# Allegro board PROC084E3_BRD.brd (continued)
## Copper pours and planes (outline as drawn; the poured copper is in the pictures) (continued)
V12V0_VSUP1 on BOTTOM (solid shape): 31.73,135.3 33.87,135.3 33.87,133.63 33.91,133.59 33.91,133.49 34.26,133.14 34.26,131.69 35.3,131.69 35.3,131.36 34.26,131.36 34.26,131.27 33.66,131.27 33.58,131.19 33.29,131.19 33.29,132.16 29.87,132.16 29.87,133.1 26.34,133.1 26.34,134.38 26.33,134.38 17.14,134.38 17.14,137.07 31.73,137.07
V12V0_VSUP2 on BOTTOM (solid shape): 31.78,144.13 33.91,144.13 33.91,142.47 33.95,142.43 33.95,142.32 34.3,141.97 34.3,140.53 35.34,140.53 35.34,140.2 34.3,140.2 34.3,140.1 33.7,140.1 33.62,140.02 33.33,140.02 33.33,141 29.91,141 29.91,141.93 26.38,141.93 26.38,143.22 26.37,143.22 17.19,143.22 17.18,143.23 17.18,146.01 31.78,146.01
V12V0_VSUP3 on BOTTOM (solid shape): 31.85,153.03 33.99,153.03 33.99,151.37 34.02,151.33 34.02,151.22 34.37,150.87 34.37,149.43 35.42,149.43 35.42,149.09 34.37,149.09 34.37,149 33.78,149 33.7,148.92 33.41,148.92 33.41,149.9 29.99,149.9 29.99,150.83 26.46,150.83 26.46,152.11 26.45,152.12 17.26,152.12 17.26,154.7 31.85,154.7
VBAT_LIN1 on BOTTOM (solid shape): 14.11,141.79 14.09,141.79 14.09,139.15 14.11,139.15 14.11,137.86 16.08,137.86 16.08,135.61 13.87,135.61 13.63,135.84 13.63,136.94 12.68,136.94 12.68,137.45 12.68,137.46 11.44,138.92 10.81,137.11 10.83,137 10.74,136.94 10.37,136.94 10.37,142.06 14.11,142.06
VBAT_LIN2 on BOTTOM (solid shape): 16.4,144.44 9.7,144.44 9.7,143.78 9.21,143.78 8.32,142.9 3.76,142.9 3.76,146.15 16.4,146.15
VBAT_LIN3 on BOTTOM (solid shape): 14.9,155.59 15.51,155.59 15.51,155.53 16.2,155.53 16.2,153.34 12.89,153.34 12.89,154.67 10.49,154.67 10.49,157.3 14.9,157.3
VCC_3V3 on TOP: 75.08,140.2 79.53,140.2 79.78,140.45 79.78,143.7 79.53,143.96 75.08,143.96 74.83,143.7 74.83,140.45
VCC_3V3 on TOP: 94.11,44.19 93.85,44.44 90.6,44.44 90.35,44.19 90.35,34.43 90.73,34.05 93.52,34.05 94.11,34.64
VCC_3V3 on BOTTOM: 39.07,114.85 39.07,111.09 39.12,111.04 40.11,111.04 40.23,111.17 40.23,114.9 40.13,115 39.22,115
VCC_3V3 on BOTTOM: 43.74,98.08 46.53,98.08 46.79,98.34 46.79,99.74 46.53,99.99 43.74,99.99 43.48,99.74 43.48,98.34
VCC_3V3 on BOTTOM: 59.74,99.74 60.55,99.74 60.68,99.86 60.68,101.39 60.88,101.59 61.54,101.59 61.85,101.89 61.85,103.65 61.7,103.8 59.82,103.8 59.69,103.67 59.69,100.7 59.61,100.62 59.61,99.86
VCC_3V3 on BOTTOM: 51,103.55 51,99.79 51.05,99.74 52.04,99.74 52.17,99.86 52.17,103.6 52.07,103.7 51.16,103.7
VCC_3V3 on L05_PWR1: 87,24.27 87,16.65 84.96,14.62 81.61,14.62 81.65,14.58 81.65,8.02 1.02,8.02 1.02,196.48 23.75,196.48 23.75,152.65 42.82,152.65 43.1,152.37 43.1,137.38 58.9,137.38 59.49,136.79 59.49,118.81 57.91,117.24 41.15,117.24 40.39,116.47 40.39,110.89 46.77,104.5 50.97,104.5 52.41,103.06 52.41,101.03 53.18,100.25 55.63,100.25 55.63,104.41 74.93,123.71 74.93,143.65 75.44,144.16 85.34,144.16 85.34,140.6 91.82,134.13 91.82,118.25 92.38,117.69 93.98,117.69 95.53,116.14 95.53,111.8 91.82,108.09 91.82,88.58 90.09,86.86 90.09,66.69 89.92,66.51 89.92,44.08 93.09,40.91 93.09,30.37 ; 40 cut-outs
VCC_5V0 on TOP: 75.34,144.46 79.43,144.46 79.68,144.72 79.68,147.82 79.43,148.07 75.34,148.07 75.08,147.82 75.08,144.72
VCC_5V0 on TOP: 90.45,68.32 92.79,68.32 92.99,68.52 99.49,68.52 99.64,68.37 99.64,65.95 99.06,65.37 93.65,65.37 92.1,66.92 90.45,66.92 90.35,67.02 90.35,68.21
VCC_5V0 on L05_PWR1: 25.15,196.48 101.19,196.48 101.19,8.02 81.99,8.02 81.99,14.14 82.14,14.29 85.01,14.29 87.38,16.65 87.38,65.75 90.45,68.82 90.45,86.45 92.2,88.2 92.2,107.99 95.28,111.06 95.28,116.96 94.23,118 74.55,118 61.82,105.27 61.77,105.27 57.09,100.59 52.99,100.59 52.99,103.03 51,105.02 48.13,105.02 40.77,112.38 40.77,130.82 25.15,146.45
VCC_12V0 on TOP: 93.9,88.86 93.9,93.54 93.65,93.79 90.12,93.79 89.87,93.54 89.87,88.74 89.1,87.98 70.69,87.98 66.75,91.91 66.75,124.01 65.05,125.71 61.25,125.71 61.23,125.69 51.4,125.69 48.67,128.42 33.37,128.42 33.35,128.44 35.11,128.44 35.11,155.56 26.78,155.56 26.78,129.21 30.55,125.44 47.08,125.44 49.61,122.9 64.29,122.9 65.61,121.58 65.61,90.06 71.48,84.19 93.98,84.19 94.84,85.05 94.84,87.92
VCC_PROFIB on TOP (solid shape): outline of 110 points within 6.93,112.51 16.94,122.29
VCC_RS485 on TOP: 29.82,119.78 29.82,104 30.35,103.47 35.94,103.47 36.35,103.88 36.35,119.78 36.07,120.06 30.1,120.06
VCC_RS485 on BOTTOM: 30.53,117.64 34.52,117.64 34.72,117.85 34.72,120.92 34.32,121.33 30.58,121.33 30.48,121.22 30.48,117.69
VDD_1V0 on BOTTOM: 59.61,97.63 59.61,93.82 58.95,93.16 58.95,91.68 59.69,90.95 61.24,90.95 61.49,91.2 61.49,95.39 61.37,95.52 60.83,95.52 60.6,95.75 60.6,97.65 59.64,97.65
VDD_1V0 on L05_PWR1: 53.85,91.71 53.85,96.66 54.36,97.17 62.23,97.17 63.68,95.72 63.68,80.05 62.23,78.6 62.23,70.25 55.5,63.51 50.04,63.51 48.77,64.78 47.57,64.78 47.35,64.56 47.35,57.85 45.34,55.84 45.34,52.01 46,51.35 55.24,51.35 57.45,53.56 60.22,53.56 60.58,53.2 60.58,52.62 59.64,51.68 59.64,39.89 58.75,39 53.72,39 51.83,40.9 51.04,40.9 50.85,41.09 50.85,43.22 49.71,44.36 49.71,44.87 50.88,46.04 50.88,47.44 49.91,48.4 39.12,48.4 35.56,51.96 35.56,57.04 34.01,58.59 34.01,58.87 35.18,60.04 35.18,62.12 42.98,69.92 51.99,69.92 53.7,71.62 53.7,74.28 52.68,75.3 52.68,75.88 54.1,77.31 54.1,78.37 52.83,79.64 40.26,79.64 35.56,84.34 35.56,87.77 34.09,89.25 34.09,89.58 35.18,90.67 35.18,93.06 36.5,94.38 41.27,94.38 45.72,89.93 52.07,89.93
VDD_1V8 on BOTTOM: 39.17,108.93 39.17,105.12 38.51,104.46 38.51,101.03 39.24,100.29 47.09,100.29 48.36,99.02 48.36,90.06 49.4,89.02 59.89,89.02 59.92,89.04 61.87,89.04 67.06,83.86 67.06,70.68 67.41,70.32 68.2,70.32 68.28,70.24 71.85,70.24 72.15,70.55 72.15,73.1 71.52,73.74 71.23,73.74 71.21,73.72 68.68,73.72 68.68,85.13 63.6,90.21 51.03,90.21 49.35,91.89 49.35,99.91 47.55,101.72 42.42,101.72 41.73,102.4 41.73,104.69 41.05,105.37 41.05,106.69 40.92,106.82 40.39,106.82 40.16,107.05 40.16,108.96 39.19,108.96
VDD_2V5 on BOTTOM: 51.1,97.63 51.1,93.82 50.44,93.16 50.44,91.68 51.18,90.95 52.73,90.95 52.98,91.2 52.98,95.39 52.86,95.52 52.32,95.52 52.1,95.75 52.1,97.65 51.13,97.65
VDD_2V5 on L05_PWR1: 50.61,100.31 53.47,97.45 53.47,91.84 51.94,90.31 45.85,90.31 41.02,95.14 37.47,95.14 35.18,92.85 35.18,84.22 40.13,79.26 52.7,79.26 53.42,78.55 53.42,77.21 52.3,76.09 52.3,75.12 53.26,74.16 53.26,71.69 51.99,70.42 42.98,70.42 35.18,62.63 35.18,51.7 38.86,48.02 49.78,48.02 50.16,47.64 50.16,40.53 48.77,39.13 32.13,39.13 29.46,41.8 29.46,90.87 30.9,92.31 30.9,96.93 35.03,101.06 40.06,101.06 43.43,97.68 45.97,97.68 48.61,100.31
VDD_IO_PHY on BOTTOM: 43.1,98.52 43.1,99.68 42.85,99.94 38.73,99.94 37.01,101.67 27.43,101.67 27.03,101.26 27.03,99.15 27.71,98.47 33.38,98.47 34.49,97.35 41.25,97.35 41.53,97.07 41.53,95.87 39.5,93.84 39.5,92.45 41.83,92.45 42.21,92.06 42.21,86.55 41.63,85.97 40.94,85.97 39.37,84.39 39.37,81.29 40.31,80.36 45.75,80.36 47.52,82.13 47.52,96.36 46.58,97.3 44.32,97.3
VDD_IO_PHY on BOTTOM: 39.52,63.06 39.52,61.86 39.6,61.79 44.7,61.79 45.36,62.45 45.59,62.22 45.59,60.7 46.91,59.37 51.66,59.37 51.89,59.6 51.89,61.76 51.23,62.42 50.27,62.42 49.58,63.11 49.58,66.11 46.69,69 35.41,69 34.92,68.52 34.92,66.84 35.13,66.64 41.58,66.64 41.63,66.59 41.63,64.23 41.27,63.87 38.96,63.87 38.89,63.79 38.89,63.44 39.12,63.21 39.37,63.21
VDD_IO_PHY on L03_SIG1: 38.96,63.67 40.67,63.67 41.43,62.91 41.43,60.29 43,58.71 49.83,58.71 53.92,62.8 53.92,67.53 54.69,68.29 58.06,68.29 58.78,69 58.78,70.27 58.1,70.95 58.1,72.85 61.65,76.39 65.02,76.39 66.47,74.94 66.47,70.04 65.02,68.59 63.63,68.59 56.61,61.58 45.01,50.64 40.16,50.64 38.79,52.01 38.79,63.49
VDD_IO_PHY on L06_SIG2: 32.59,94.2 46.66,94.2 47.6,93.26 47.6,82.01 40.03,74.44 40.03,70.83 35.2,66 27.38,66 25.91,67.48 25.91,87.52
VDD_IO_PHY on L06_SIG2: 60.27,67.12 62.31,69.15 62.31,83.5 62.03,83.78 58.75,83.78 57.89,82.92 57.89,72.96 57.45,72.53 53.98,72.53 53.62,72.18 53.62,67.48 53.98,67.12
VDD_IO_PHY on L06_SIG2: 56.62,51.93 56.62,49.21 59.61,46.22 59.61,39.87 56.87,37.12 56.87,33.06 55.35,31.54 50.7,31.54 48.64,33.59 48.64,35.04 48.56,35.04 46.05,37.56 46.05,44.72 47.17,45.84 47.17,52.54 48.6,53.98 48.6,55.63 50.01,57.04 50.01,58.61 51.1,59.7 53.9,59.7 54.79,58.82 54.79,53.15 55.32,52.62 55.93,52.62 ; 4 cut-outs
(no net) on TOP: 16.94,119.93 16.94,117.46 16.69,117.21 13.87,117.21 13.49,116.83 13.49,113.35 12.65,112.51 6.93,112.51 6.93,116.42 8.2,117.69 11.38,117.69 14.25,120.56 14.25,122.09 14.45,122.29 16.38,122.29 16.38,120.49
(no net) on TOP: 14.71,125.85 14.71,123.08 14.83,122.95 16.46,122.95 17.37,122.04 21.51,122.04 21.64,122.16 21.64,125.95 21.26,126.33 15.19,126.33
(no net) on TOP: 21.18,117.24 18.03,117.24 17.78,117.49 17.78,120.23 17.35,120.66 17.35,121.4 17.55,121.6 21.36,121.6 21.54,121.43 21.54,117.59
(no net) on BOTTOM: 1.02,8.02 1.02,196.48 101.19,196.48 101.19,8.02 ; 151 cut-outs
(no net) on BOTTOM: 10.37,142.06 10.37,136.94 13.63,136.94 13.63,135.61 16.08,135.61 16.08,137.86 14.11,137.86 14.11,142.06
(no net) on BOTTOM: 26.38,143.23 26.38,141.93 29.91,141.93 29.91,141 33.33,141 33.33,140.02 35.37,140.02 35.37,140.59 34.31,140.59 34.31,142.07 33.91,142.47 33.91,144.13 31.78,144.13 31.78,146.01 17.18,146.01 17.18,143.22 26.37,143.22
(no net) on BOTTOM: 26.34,134.39 26.34,133.1 29.87,133.1 29.87,132.16 33.29,132.16 33.29,131.19 35.33,131.19 35.33,131.75 34.27,131.75 34.27,133.23 33.87,133.63 33.87,135.3 31.73,135.3 31.73,137.07 17.14,137.07 17.14,134.38 26.33,134.38
(no net) on BOTTOM: 10.49,157.3 10.49,154.67 12.89,154.67 12.89,153.34 16.2,153.34 16.2,155.59 14.9,155.59 14.9,157.3
(no net) on BOTTOM: 16.4,144.44 16.4,146.15 3.76,146.15 3.76,142.9 9.7,142.9 9.7,144.44
(no net) on BOTTOM: 26.46,152.13 26.46,150.83 29.99,150.83 29.99,149.9 33.41,149.9 33.41,148.92 35.45,148.92 35.45,149.49 34.39,149.49 34.39,150.96 33.99,151.37 33.99,153.03 31.85,153.03 31.85,154.7 17.26,154.7 17.26,152.12 26.45,152.12
(no net) on L03_SIG1: 1.02,8.02 1.02,196.48 101.19,196.48 101.19,8.02 ; 125 cut-outs
(no net) on L06_SIG2: 1.02,8.02 1.02,196.48 101.19,196.48 101.19,45.2 72.31,45.2 72.31,8.02 ; 142 cut-outs
BP/MC_PRG1_UART0_RXD on TOP (solid shape): 71.07,142.91 71.25,142.06 70.04,141.77 69.95,141.79 69.93,141.88 70.22,143.09
BP_PRG1_PWM0_B1 on TOP (solid shape): 58.37,188.63 58.55,187.78 57.34,187.49 57.25,187.51 57.23,187.6 57.52,188.81
BP_PRG1_PWM0_B2 on TOP (solid shape): 55.83,188.63 56.01,187.78 54.8,187.49 54.71,187.51 54.69,187.6 54.98,188.81
BP_PRG1_PWM3_A0 on TOP (solid shape): 76.89,185.22 76.19,184.52 76.13,184.5 76.08,184.52 75.37,185.22 76.13,186.09
CAN1_H on BOTTOM (solid shape): 6.66,161.98 6.68,161.94 6.66,161.9 5.98,161.22 5.06,161.94 5.98,162.66
CAN2_H on BOTTOM (solid shape): 12.51,167.95 12.52,167.91 12.51,167.87 11.82,167.18 10.91,167.91 11.82,168.63
CAN3_H on BOTTOM (solid shape): 6.66,174.68 6.68,174.64 6.66,174.6 5.98,173.92 5.06,174.64 5.98,175.36
CAN4_H on BOTTOM (solid shape): 12.51,180.27 12.52,180.23 12.51,180.19 11.82,179.5 10.91,180.23 11.82,180.95
CAN5_H on BOTTOM (solid shape): 6.66,186.11 6.68,186.07 6.66,186.03 5.98,185.35 5.06,186.07 5.98,186.79
CAN6_H on BOTTOM (solid shape): 12.51,192.59 12.52,192.55 12.51,192.51 11.82,191.82 10.91,192.55 11.82,193.27
EHRPWM0_A on L06_SIG2 (solid shape): 79.29,28.81 79.33,28.8 79.34,28.75 79.12,27.54 78.22,27.69 78.07,28.59
EHRPWM0_B on L06_SIG2 (solid shape): 76.75,28.81 76.79,28.8 76.8,28.75 76.58,27.54 75.68,27.69 75.53,28.59
EHRPWM1_A on L06_SIG2 (solid shape): 74.21,28.81 74.25,28.8 74.26,28.75 74.04,27.54 73.14,27.69 72.99,28.59
EHRPWM1_B on L06_SIG2 (solid shape): 84.74,31.29 84.75,31.34 84.8,31.35 86.02,31.13 85.86,30.23 84.97,30.08
EHRPWM2_A on L06_SIG2 (solid shape): 81.88,29.19 81.87,29.14 81.83,29.13 80.61,29.35 80.76,30.25 81.66,30.41
ETH_EARTH on TOP: 1.19,14.32 1.19,88.2 1.52,88.53 20.8,88.53 21.51,87.82 21.51,84.85 20.71,84.05 15.92,84.05 14.76,85.21 6.68,85.21 5.77,84.29 5.77,69.15 6.5,68.42 21.74,68.42 22.73,69.41 24.13,69.41 24.69,68.85 24.69,63.55 24.17,63.02 20.84,63.02 20.69,62.88 20.69,59.02 20.36,58.69 14.43,58.69 13.26,59.86 6.71,59.86 5.77,58.92 5.77,43.63 6.63,42.76 21.62,42.76 22.86,44.01 24.08,44.01 24.69,43.4 24.69,41.24 22.02,38.57 13.61,38.57 12.22,37.18 12.22,13.45 11.48,12.71 2.79,12.71 ; 7 cut-outs
ETH_EARTH on BOTTOM: 2.79,12.71 11.48,12.71 12.22,13.45 12.22,37.18 13.61,38.57 22.02,38.57 24.69,41.24 24.69,43.4 24.08,44.01 22.86,44.01 21.62,42.76 6.63,42.76 5.77,43.63 5.77,58.92 6.71,59.86 13.26,59.86 14.43,58.69 20.42,58.69 20.72,58.99 20.72,62.45 20.29,62.88 5.33,62.88 4.83,63.39 4.83,65.42 5.21,65.8 24.05,65.8 24.69,66.44 24.69,68.85 24.13,69.41 22.73,69.41 21.74,68.42 6.5,68.42 5.77,69.15 5.77,84.29 6.68,85.21 14.76,85.21 15.92,84.04 20.71,84.04 21.51,84.85 21.51,87.82 20.8,88.53 1.52,88.53 1.19,88.2 1.19,14.32
ETH_EARTH on L02_GND1: 2.79,12.71 11.48,12.71 12.22,13.45 12.22,37.18 13.61,38.57 22.02,38.57 24.69,41.24 24.69,43.4 24.08,44.01 22.86,44.01 21.62,42.76 6.63,42.76 5.77,43.63 5.77,58.92 6.71,59.86 13.26,59.86 14.43,58.69 20.35,58.69 20.7,59.04 20.7,62.46 20.28,62.88 5.33,62.88 4.83,63.39 4.83,65.42 5.21,65.8 24.05,65.8 24.69,66.44 24.69,68.85 24.13,69.41 22.73,69.41 21.74,68.42 6.5,68.42 5.77,69.15 5.77,84.29 6.68,85.21 14.76,85.21 15.92,84.04 20.71,84.04 21.51,84.85 21.51,87.82 20.8,88.53 1.52,88.53 1.19,88.2 1.19,14.32
ETH_EARTH on L03_SIG1: 1.19,14.32 1.19,88.2 1.52,88.53 20.8,88.53 21.51,87.82 21.51,84.85 20.71,84.04 15.92,84.04 14.76,85.21 6.68,85.21 5.77,84.29 5.77,69.15 6.5,68.42 21.74,68.42 22.73,69.41 24.13,69.41 24.69,68.85 24.69,66.44 24.05,65.8 5.21,65.8 4.83,65.42 4.83,63.39 5.33,62.88 24.26,62.88 24.53,62.61 24.2,62.28 20.9,62.28 20.7,62.08 20.7,59.03 20.35,58.69 14.43,58.69 13.26,59.86 6.71,59.86 5.77,58.92 5.77,43.63 6.63,42.76 21.62,42.76 22.86,44.01 24.08,44.01 24.69,43.4 24.69,41.24 22.02,38.57 13.61,38.57 12.22,37.18 12.22,13.45 11.48,12.71 2.79,12.71 ; 2 cut-outs
ETH_EARTH on L04_GND2: 2.79,12.71 11.48,12.71 12.22,13.45 12.22,37.18 13.61,38.57 22.02,38.57 24.69,41.24 24.69,43.4 24.08,44.01 22.86,44.01 21.62,42.76 6.63,42.76 5.77,43.63 5.77,58.92 6.71,59.86 13.26,59.86 14.43,58.69 20.31,58.69 20.68,59.06 20.68,62.45 20.25,62.88 5.33,62.88 4.83,63.39 4.83,65.42 5.21,65.8 24.05,65.8 24.69,66.44 24.69,68.85 24.13,69.41 22.73,69.41 21.74,68.42 6.5,68.42 5.77,69.15 5.77,84.29 6.68,85.21 14.76,85.21 15.92,84.05 20.71,84.05 21.51,84.85 21.51,87.82 20.8,88.53 1.52,88.53 1.19,88.2 1.19,14.32
ETH_EARTH on L05_PWR1: 2.79,12.71 11.48,12.71 12.22,13.45 12.22,37.18 13.61,38.57 22.02,38.57 24.69,41.24 24.69,43.4 24.08,44.01 22.86,44.01 21.62,42.76 6.63,42.76 5.77,43.63 5.77,58.92 6.71,59.86 13.26,59.86 14.43,58.69 20.31,58.69 20.69,59.07 20.69,62.5 20.31,62.88 5.33,62.88 4.83,63.39 4.83,65.42 5.21,65.8 24.05,65.8 24.69,66.44 24.69,68.85 24.13,69.41 22.73,69.41 21.74,68.42 6.5,68.42 5.77,69.15 5.77,84.29 6.68,85.21 14.76,85.21 15.92,84.04 20.7,84.04 21.51,84.85 21.51,87.82 20.8,88.53 1.52,88.53 1.19,88.2 1.19,14.32
ETH_EARTH on L06_SIG2: 2.79,12.71 11.48,12.71 12.22,13.45 12.22,37.18 13.61,38.57 22.02,38.57 24.69,41.24 24.69,43.4 24.08,44.01 22.86,44.01 21.62,42.76 6.63,42.76 5.77,43.63 5.77,58.92 6.71,59.86 13.26,59.86 14.43,58.69 20.37,58.69 20.7,59.02 20.7,62.5 20.32,62.88 5.33,62.88 4.83,63.39 4.83,65.42 5.21,65.8 24.05,65.8 24.69,66.44 24.69,68.85 24.13,69.41 22.73,69.41 21.74,68.42 6.5,68.42 5.77,69.15 5.77,84.29 6.68,85.21 14.76,85.21 15.93,84.03 20.69,84.03 21.51,84.85 21.51,87.82 20.8,88.53 1.52,88.53 1.19,88.2 1.19,14.32
ETH_EARTH on L07_GND: 2.79,12.71 11.48,12.71 12.22,13.45 12.22,37.18 13.61,38.57 22.02,38.57 24.69,41.24 24.69,43.4 24.08,44.01 22.86,44.01 21.62,42.76 6.63,42.76 5.77,43.63 5.77,58.92 6.71,59.86 13.26,59.86 14.43,58.69 20.37,58.69 20.73,59.05 20.73,62.44 20.29,62.88 5.33,62.88 4.83,63.39 4.83,65.42 5.21,65.8 24.05,65.8 24.69,66.44 24.69,68.85 24.13,69.41 22.73,69.41 21.74,68.42 6.5,68.42 5.77,69.15 5.77,84.29 6.68,85.21 14.76,85.21 15.93,84.04 20.7,84.04 21.51,84.85 21.51,87.82 20.8,88.53 1.52,88.53 1.19,88.2 1.19,14.32
LIN5_DATA on BOTTOM (solid shape): 12.91,151.99 12.88,151.91 12.8,151.89 11.58,152.15 11.75,153.05 12.64,153.22
LIN6_DATA on BOTTOM (solid shape): 12.7,151.52 12.77,151.5 12.8,151.43 12.66,150.37 11.75,150.48 11.65,151.39
MCAN5_RX on BOTTOM (solid shape): 30.24,163.86 30.42,163.02 29.21,162.73 29.13,162.75 29.11,162.83 29.4,164.04
MCAN6_RX on BOTTOM (solid shape): 30.24,170.08 30.42,169.24 29.21,168.95 29.13,168.97 29.11,169.05 29.4,170.27
MCAN7_RX on BOTTOM (solid shape): 30.24,176.05 30.4,175.2 29.25,174.96 29.17,174.98 29.15,175.06 29.39,176.21
MCAN7_RX on L03_SIG1 (solid shape): 31.25,177.13 31.3,177.11 31.31,177.07 31.06,175.86 30.22,176.03 30.05,176.87
MCAN7_TX on L03_SIG1 (solid shape): 31.31,177.55 31.3,177.5 31.25,177.49 30.05,177.74 30.22,178.59 31.06,178.75
MCAN9_TX on L03_SIG1 (solid shape): 30.23,184.55 30.4,183.71 29.2,183.46 29.15,183.47 29.14,183.52 29.39,184.72
MCAN11_RX on BOTTOM (solid shape): 30.24,188.37 30.4,187.52 29.25,187.28 29.17,187.3 29.15,187.38 29.39,188.53
MCAN11_RX on L03_SIG1 (solid shape): 31.25,189.44 31.3,189.43 31.31,189.38 31.06,188.18 30.22,188.35 30.05,189.19
MCAN11_TX on L03_SIG1 (solid shape): 31.31,189.87 31.3,189.82 31.25,189.81 30.05,190.06 30.22,190.9 31.06,191.07
MCU_ADC1_AIN0 on L06_SIG2 (solid shape): 71.06,145.44 71.23,144.6 70.02,144.34 69.98,144.36 69.96,144.4 70.22,145.61
MCU_ADC1_AIN1 on L06_SIG2 (solid shape): 68.52,145.44 68.69,144.6 67.48,144.34 67.44,144.36 67.42,144.4 67.68,145.61
MCU_ADC1_AIN2 on L06_SIG2 (solid shape): 65.98,145.44 66.15,144.6 64.94,144.34 64.9,144.36 64.88,144.4 65.14,145.61
MCU_ADC1_AIN3 on L06_SIG2 (solid shape): 63.44,145.44 63.61,144.6 62.4,144.34 62.36,144.36 62.34,144.4 62.6,145.61
PERIPH_RSTZ on L03_SIG1 (solid shape): 67.06,187.58 67.05,187.54 67,187.52 65.79,187.78 65.96,188.62 66.8,188.79
PROFIB_GND on TOP (solid shape): 21.64,125.95 21.64,122.16 21.51,122.04 17.37,122.04 16.76,122.65 16.76,122.67 16.74,122.67 16.69,122.72 16.69,123.03 14.91,123.03 14.91,122.95 14.83,122.95 14.71,123.08 14.71,125.85 15.19,126.33 21.26,126.33
PROFIB_GND on TOP: 8.46,102.76 16.38,102.76 17.69,101.45 17.69,94.59 17.93,94.35 22.17,94.35 22.58,94.76 22.58,127.14 22.28,127.45 16.18,127.45 14.25,125.52 14.25,123.38 14.68,122.95 16.46,122.95 17.65,121.76 17.65,117.39 17.09,116.83 14.68,116.83 14.2,116.35 14.2,112.51 13.72,112.03 7.65,112.03 6.93,111.32 6.93,104.28
PROFIB_GND on TOP: 17.93,94.35 22.17,94.35 22.43,94.6 22.43,100.83 22.17,101.08 17.93,101.08 17.68,100.83 17.68,94.6
PROFIB_GND on BOTTOM, L02_GND1, L03_SIG1, L04_GND2, L05_PWR1, L06_SIG2, L07_GND: 8.46,102.76 16.38,102.76 17.69,101.45 17.69,94.59 17.93,94.35 22.17,94.35 22.58,94.76 22.58,127.14 22.28,127.45 16.18,127.45 14.25,125.52 14.25,120.51 11.4,117.67 8.18,117.67 6.93,116.42 6.93,104.28
RMII8_AVD33 on BOTTOM: 30.76,25.77 30.76,28.97 30.48,29.25 30.48,30.04 30.43,30.09 29.69,30.09 29.64,30.04 29.64,25.9 29.77,25.77
SHLD_PROFIB_GND on TOP, BOTTOM, L02_GND1, L03_SIG1, L04_GND2, L05_PWR1, L06_SIG2, L07_GND: 16.66,93.94 16.97,94.25 16.97,101.01 16.03,101.95 8.13,101.95 6.48,103.6 6.48,117.16 7.67,118.35 11.15,118.35 13.87,121.07 13.87,125.77 13.08,126.56 1.35,126.56 1.09,126.3 1.09,94.1 1.24,93.94
SPI3_CS1 on BOTTOM (solid shape): 73.61,188.63 73.79,187.78 72.58,187.49 72.49,187.51 72.47,187.6 72.76,188.81
SPI3_CS2 on BOTTOM (solid shape): 71.07,188.63 71.25,187.78 70.04,187.49 69.95,187.51 69.93,187.6 70.22,188.81
SPI3_D0 on L03_SIG1 (solid shape): 63.44,188.62 63.61,187.78 62.4,187.52 62.36,187.54 62.34,187.58 62.6,188.79
SPI3_D1 on L03_SIG1 (solid shape): 61.92,189.7 61.97,189.68 61.98,189.64 61.72,188.43 60.88,188.6 60.71,189.44
TH_EHRPWM0_SYNCI on BOTTOM (solid shape): 87.45,27.63 87.47,27.57 87.45,27.51 86.73,26.99 85.83,27.7 86.75,28.33
TH_UART4_CTSN on L06_SIG2 (solid shape): 66.96,28.75 66.97,28.8 67.02,28.81 68.24,28.59 68.08,27.69 67.19,27.54
TH_UART4_TXD on L06_SIG2 (solid shape): 69.5,28.75 69.51,28.8 69.56,28.81 70.78,28.59 70.62,27.69 69.73,27.54
UART3_CTSN on BOTTOM (solid shape): 58.37,186.09 58.55,185.24 57.34,184.95 57.25,184.97 57.23,185.06 57.52,186.27
UART3_RTSN on BOTTOM (solid shape): 59.77,187.08 59.79,187.17 59.88,187.19 61.09,186.9 60.91,186.05 60.06,185.87
VSYS_IO_1V8 on TOP: 90.55,77.31 92.2,77.31 92.33,77.43 92.33,79.09 92.99,79.75 94.26,79.75 94.56,79.44 94.56,77.61 93.98,77.03 93.22,77.03 92.18,75.99 90.53,75.99 90.45,76.06 90.45,77.21
VSYS_IO_3V3 on TOP: 90.58,73.85 92.63,73.85 92.68,73.9 97.66,73.9 98.12,74.36 98.12,77.46 94.97,80.61 71.2,80.61 63.68,88.13 63.68,100.85 62.53,102 54.61,102 51.08,105.53 48.62,105.53 42.62,111.52 42.62,113.93 42.88,114.19 45.14,114.19 51.1,108.22 62.23,108.22 64.97,105.48 64.97,90.16 72.67,82.46 95.81,82.46 99.57,78.7 99.57,72 99.24,71.67 92.91,71.67 92.18,72.4 90.55,72.4 90.45,72.51 90.45,73.73
N23015059 on TOP (solid shape): 21.54,121.43 21.54,117.59 21.18,117.24 18.03,117.24 17.78,117.49 17.78,120.23 17.35,120.66 17.35,121.4 17.55,121.6 21.36,121.6
N23749024 on TOP (solid shape): 4.41,35.44 4.44,35.52 4.52,35.54 5.73,35.25 5.55,34.41 4.7,34.23

Small or netless copper shapes (teardrops, artwork), in the pictures only: 624 on TOP, 728 on BOTTOM, 274 on L03_SIG1, 236 on L06_SIG2

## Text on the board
Ref Des/Assembly Bottom: BOTTOM ASSEMBLY REV E2 | J7X GESI EXP BRD PROC084
Ref Des/Silkscreen Bottom: MC7 | MC5 | MC11 | MCAN | SW:ON LIN | MASTER MODE | GND | MOTOR CONTROL | BP-RHS | BP-LHS | SENSOR | USS/IMU | See ti.com/tool/J7EXPC01EVM" | 5V | "Limited BoosterPack support. | 3V3 | TEST | MC4 | MC9 | LIN3,4 | MC6 | LIN1,2 | LIN5,6 | PROFI BUS | RMII8 | PRG0_RGMII1_B | PRG1_RGMII1_B | PRG0_RGMII2_T | PRG1_RGMII2_T | J7EXPC01EVM | J7X GESI EXP BRD | PCB#: PROC084E3
User.Comments: A | B | C | D | E | 1 | 2 | 3 | 4 | 5 | 36 | 35 | 14 | 12 | 10 | 8 | 6 | 13 | 11 | 9 | 7 | F | G | H | J | K | L | M | N | P | card ejected | fully inserted | ejection | 119 | 59 | 60 | 120 | 40 | 39 | BOARD NAME: | J7X GESI EXP BRD | REV: E3 | DATE: 21/11/2019 | DESCRIPTION: | SHEET | OF | 15 | PROC084 | SCALE: 1 | CR_STD1_3 | CR_STD1_2 | CR_2_2 | CR_ETHERNET_1 | TEXAS INSTRUMENTS | CR_T1_5 | BASY CP CARD REV E3
Ref Des/Assembly Top: J7X GESI EXP BRD PROC084 | TOP ASSEMBLY REV E2
Ref Des/Silkscreen Top: NOT FCC APPROVED FOR RESALE | FOR EVALUATION ONLY;
PAGE_OUTLINE: 15. | REMOVE THE UNUSED PADS IN ALL INTERNAL LAYERS. | ALL THE IMPEDANCE SHALL BE MATCHED AS PER IMPEDANCE TABLE WITH +/-10% TOLERANCE. | VIA HOLES SHALL BE FILLED WITH NON CONDUCTIVE INK AND COVERED WITH SOLDER MASK. ONLY SOLDER MASK IMAGES | LAYOUT BY | REVIEWED BY | APPROVED BY | SIGNATURES | AMB | VU | ZA | DATE | 211119 | SIZE | SCALE: | D | NONE | SHEET 1 OF 15 | PROC084 | Rev | E3 | DETAIL-A | TEXAS INSTRUMENTS | J7X GESI EXP BRD
User.8: k | ejection | fully inserted | card ejected | BASY C5545BP REV.B
User.20: GROUND-PLANE-05 | 16
User.23: INNER-SIGNAL-04 | 15
User.36: 02 | 03 | 04 | 05 | STRIPLINE | MICROSTRIP | EDGE COUPLED MICROSTRIP | L1,L8 | L8 | L3,L6 | 6.8 | 5.0 | 4.0 | NA | 7.3 | 12.0 | 6.5 | 50 | 120 | 150 | 100 | L2,L7 | L5 | L6 | L2/L4,L5/L7
User.37: LAYER NAME | 0.0047 | 0.0050 | 0.0070 | 0.0280 | LAYER STACKUP | FINISHED Cu | 1oz. | X-SECTION | DIELECTRIC THICKNESS | [INCHES] | L01 | L02 | L03 | L04 | L05 | L06 | L07 | L08 | PRIMARY SIDE | PRIMARY SIDE SILKSCREEN | PRIMARY SIDE SOLDERMASK | GROUND-PLANE-1 | INNER-SIGNAL-1 | GROUND-PLANE-2 | POWER-PLANE-01 | INNER-SIGNAL-2 | GROUND-PLANE-3 | SECONDARY SIDE | SECONDARY SIDE SOLDERMASK | SECONDARY SIDE SILKSCREEN
User.41: FIGURE | SIZE | 8.0 | 32.0 | 36.0 | 40.0 | 44.0 | 66.0 | 126.0 | DRILL CHART: TOP to BOTTOM | ALL UNITS ARE IN MILS | TOLERANCE | +3.0/-3.0 | +2.0/-2.0 | PLATED | NON-PLATED | QTY | 1363 | 10 | 135 | 56 | 11 | 30 | 16 | 2 | 4 | 14
User.42: 3 - Board assembly must comply with workmanship standards IPC-A-610 Class 2, unless otherwise specified. | 1 - All MSL components should be baked as per JEDEC standard. | 2 - PCB should be baked at 120 degree for 8 hours. | 4 - These assemblies are ESD sensitive, ESD precautions shall be observed. | 5 - These assemblies must be clean and free from flux and all contaminants. Use of no clean flux is not acceptable. | 6 - Provide serial numbers to the assembled boards for identification. | ASSEMBLY NOTES:- | 7 - The assembled board are wrapped in ESD Covers(individual) and packed securely before shipment. | PROC084 E2 ASSEMBLY TOP
User.45: PROC084 E2 ASSEMBLY BOTTOM | 7 - The assembled board are wrapped in ESD Covers(individual) and packed securely before shipment. | ASSEMBLY NOTES:- | 5 - These assemblies must be clean and free from flux and all contaminants. Use of no clean flux is not acceptable. | 6 - Provide serial numbers to the assembled boards for identification. | 2 - PCB should be baked at 120 degree for 8 hours. | 4 - These assemblies are ESD sensitive, ESD precautions shall be observed. | 1 - All MSL components should be baked as per JEDEC standard. | 3 - Board assembly must comply with workmanship standards IPC-A-610 Class 2, unless otherwise specified.
